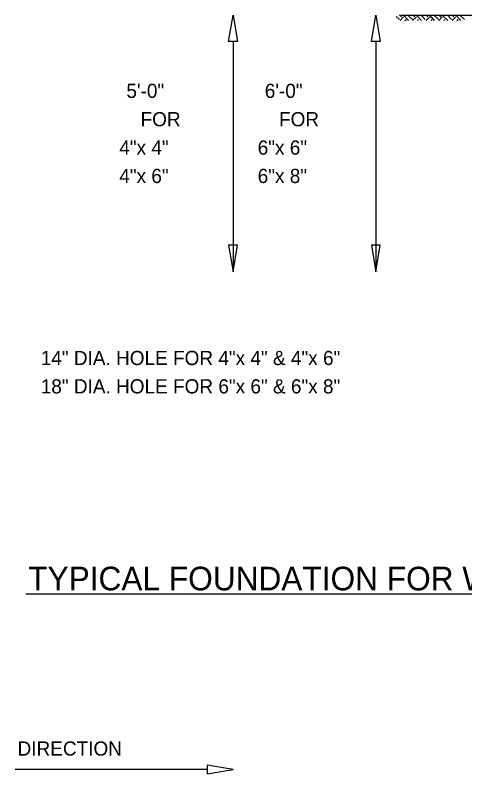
# Model space of a CAD drawing. Extents: x -2137320.7 to -2137313.2, y -2137946.3 to -2137936.1.
# Drawn here: x -2137319.453 to -2137317.553, y -2137939.661 to -2137936.452 of the extents above; entities that cross this region are included whole.
import ezdxf

# ---------------------------------------------------------------- set-up
doc = ezdxf.new("R2010")
doc.units = 0
for name, color, linetype in [('DETL-DIMS', 7, 'Continuous'), ('DETL-LINE', 7, 'Continuous'), ('DETL-NOTE', 7, 'Continuous'), ('DETL-PATT', 7, 'Continuous'), ('DETL-TITL', 7, 'Continuous')]:
    doc.layers.add(name, color=color, linetype=linetype)

msp = doc.modelspace()

# ---------------------------------------------------------------- linework, layer by layer
at = {"layer": 'DETL-DIMS'}
for p, q in [((-2137318.527, -2137936.452), (-2137318.527, -2137936.452)), ((-2137317.923, -2137936.452), (-2137317.923, -2137936.452)), ((-2137318.532, -2137936.564), (-2137318.532, -2137937.537)), ((-2137317.928, -2137936.564), (-2137317.928, -2137937.537)), ((-2137318.527, -2137937.537), (-2137318.527, -2137937.537)), ((-2137317.923, -2137937.537), (-2137317.923, -2137937.537)), ((-2137318.641, -2137939.642), (-2137319.453, -2137939.642))]:
    msp.add_line(p, q, dxfattribs=at)
for points in [[(-2137318.514, -2137936.564), (-2137318.551, -2137936.564), (-2137318.532, -2137936.452)], [(-2137317.91, -2137936.564), (-2137317.947, -2137936.564), (-2137317.928, -2137936.452)], [(-2137318.514, -2137937.425), (-2137318.551, -2137937.425), (-2137318.532, -2137937.537)], [(-2137317.91, -2137937.425), (-2137317.947, -2137937.425), (-2137317.928, -2137937.537)], [(-2137318.641, -2137939.625), (-2137318.641, -2137939.661), (-2137318.532, -2137939.642)]]:
    msp.add_lwpolyline(points, close=True, dxfattribs=at)
at = {"layer": 'DETL-LINE'}
msp.add_line((-2137317.822, -2137936.452), (-2137317.479, -2137936.452), dxfattribs=at)
at = {"layer": 'DETL-PATT'}
for p, q in [((-2137317.829, -2137936.47), (-2137317.843, -2137936.457)), ((-2137317.82, -2137936.459), (-2137317.828, -2137936.452)), ((-2137317.826, -2137936.475), (-2137317.812, -2137936.459)), ((-2137317.82, -2137936.452), (-2137317.818, -2137936.452)), ((-2137317.791, -2137936.475), (-2137317.812, -2137936.452)), ((-2137317.774, -2137936.47), (-2137317.793, -2137936.452)), ((-2137317.764, -2137936.459), (-2137317.773, -2137936.452)), ((-2137317.773, -2137936.475), (-2137317.757, -2137936.459)), ((-2137317.764, -2137936.452), (-2137317.763, -2137936.452)), ((-2137317.736, -2137936.475), (-2137317.757, -2137936.452)), ((-2137317.72, -2137936.47), (-2137317.737, -2137936.452)), ((-2137317.709, -2137936.459), (-2137317.716, -2137936.452)), ((-2137317.716, -2137936.475), (-2137317.701, -2137936.459)), ((-2137317.709, -2137936.452), (-2137317.708, -2137936.452)), ((-2137317.681, -2137936.475), (-2137317.701, -2137936.452)), ((-2137317.664, -2137936.47), (-2137317.683, -2137936.452)), ((-2137317.654, -2137936.459), (-2137317.662, -2137936.452)), ((-2137317.662, -2137936.475), (-2137317.648, -2137936.459)), ((-2137317.654, -2137936.452), (-2137317.654, -2137936.452)), ((-2137317.624, -2137936.475), (-2137317.648, -2137936.452)), ((-2137317.609, -2137936.47), (-2137317.626, -2137936.452)), ((-2137317.599, -2137936.459), (-2137317.606, -2137936.452)), ((-2137317.606, -2137936.475), (-2137317.591, -2137936.459)), ((-2137317.599, -2137936.452), (-2137317.598, -2137936.452)), ((-2137317.57, -2137936.475), (-2137317.591, -2137936.452)), ((-2137317.554, -2137936.47), (-2137317.573, -2137936.452)), ((-2137317.806, -2137936.475), (-2137317.801, -2137936.47)), ((-2137317.751, -2137936.475), (-2137317.748, -2137936.47)), ((-2137317.695, -2137936.475), (-2137317.691, -2137936.47)), ((-2137317.641, -2137936.475), (-2137317.637, -2137936.47)), ((-2137317.586, -2137936.475), (-2137317.581, -2137936.47))]:
    msp.add_line(p, q, dxfattribs=at)
at = {"layer": 'DETL-TITL'}
msp.add_line((-2137319.4077, -2137938.899), (-2137315.8737, -2137938.899), dxfattribs=at)

# ---------------------------------------------------------------- texts
at = {"layer": 'DETL-NOTE'}
for s, p in [('5\'-0"', (-2137318.983, -2137936.802)), ('6\'-0"', (-2137318.398, -2137936.802)), ('FOR', (-2137318.923, -2137936.922)), ('FOR', (-2137318.338, -2137936.922)), ('4"x 4"', (-2137319.013, -2137937.042)), ('6"x 6"', (-2137318.428, -2137937.042)), ('4"x 6"', (-2137319.013, -2137937.162)), ('6"x 8"', (-2137318.428, -2137937.162)), ('14" DIA. HOLE FOR 4"x 4" & 4"x 6"', (-2137319.345, -2137937.932)), ('18" DIA. HOLE FOR 6"x 6" & 6"x 8"', (-2137319.345, -2137938.052)), ('DIRECTION', (-2137319.443, -2137939.584))]:
    msp.add_text(s, height=0.06, dxfattribs=at).set_placement(p)
at = {"layer": 'DETL-TITL'}
msp.add_text('TYPICAL FOUNDATION FOR WOOD SUPPORTS', height=0.100002, dxfattribs=at).set_placement((-2137319.398, -2137938.885))

doc.saveas('drawing.dxf')
